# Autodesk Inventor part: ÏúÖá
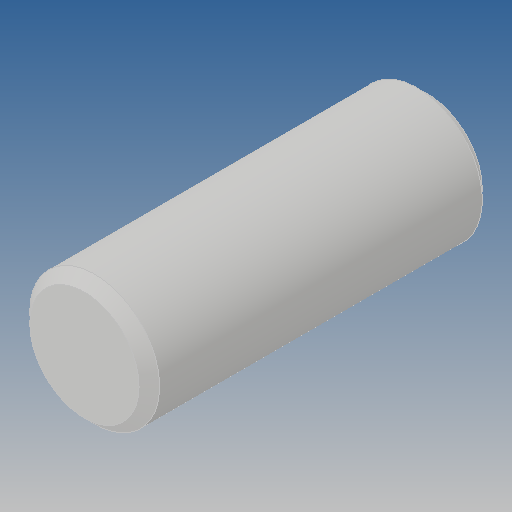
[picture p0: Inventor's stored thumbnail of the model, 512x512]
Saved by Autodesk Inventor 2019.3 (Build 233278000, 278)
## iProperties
Created: 2017-08
Part Number: ÏúÖá
Material: Ogólny
Document SubType Name: Modeling
Designer: Admin
Density: 1 g/cm^3
Appearance: Domyślna
Author: Admin
Revision Number: ÈÎºÎ
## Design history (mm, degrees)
feature "ÊäÈë1"
node "Bryła1"
